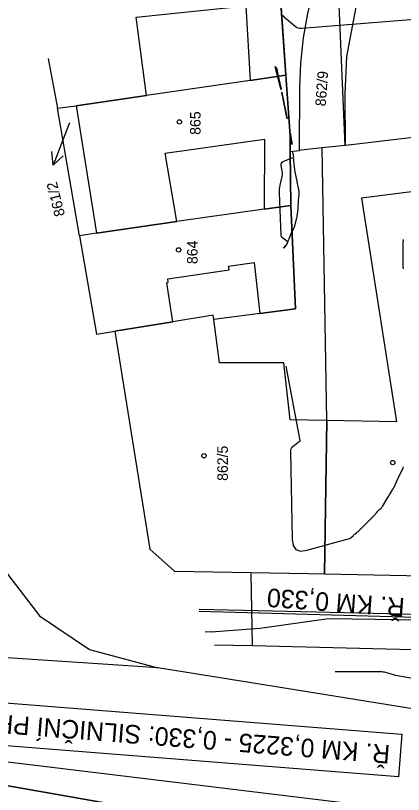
# Model space of a CAD drawing. Extents: x -534481 to -534256, y -1190577 to -1190138.
# Drawn here: x -534381.4 to -534350, y -1190249.6 to -1190186.6 of the extents above; entities that cross this region are included whole.
import ezdxf

# ---------------------------------------------------------------- set-up
doc = ezdxf.new("R2010")
doc.units = 0
for name, color, linetype in [('14', 7, 'Continuous'), ('30', 7, 'Continuous'), ('31', 7, 'Continuous'), ('_N_text', 7, 'Continuous'), ('_rámeček', 7, 'Continuous'), ('_tenka', 7, 'Continuous'), ('Hranice parcel', 7, 'Continuous'), ('Level 30', 7, 'Continuous'), ('Parcelní čísla', 7, 'Continuous'), ('Polygon budovy', 7, 'Continuous'), ('Pop  PČ popisy', 7, 'Continuous'), ('Vrstva 1', 7, 'Continuous'), ('Značky budov', 7, 'Continuous')]:
    doc.layers.add(name, color=color, linetype=linetype)

msp = doc.modelspace()

# ---------------------------------------------------------------- linework, layer by layer
at = {"layer": '14'}
for points in [[(-534362.202, -1190237.552), (-534362.331, -1190231.681)], [(-534316.429, -1190238.25), (-534318.08, -1190238.03), (-534322.04, -1190237.08), (-534332.22, -1190235.41), (-534338.777, -1190234.334), (-534339.342, -1190238.274), (-534345.981, -1190237.953), (-534362.202, -1190237.552), (-534365.29, -1190237.5)]]:
    msp.add_lwpolyline(points, dxfattribs=at)
at = {"layer": '30'}
for points in [[(-534360.382, -1190190.677), (-534360.38, -1190190.668), (-534360.373, -1190190.673), (-534360.359, -1190190.692), (-534360.294, -1190190.794), (-534360.279, -1190190.82), (-534360.266, -1190190.847), (-534360.256, -1190190.875), (-534360.248, -1190190.904), (-534360.158, -1190191.324), (-534359.931, -1190192.369), (-534359.903, -1190192.507), (-534359.895, -1190192.553), (-534359.91, -1190192.508), (-534359.946, -1190192.372), (-534360.377, -1190190.7)], [(-534359.433, -1190194.812), (-534359.44, -1190194.779), (-534359.467, -1190194.648), (-534359.474, -1190194.615), (-534359.481, -1190194.582), (-534359.487, -1190194.55), (-534359.494, -1190194.517), (-534359.728, -1190193.318), (-534359.736, -1190193.278), (-534359.744, -1190193.239), (-534359.753, -1190193.199), (-534359.762, -1190193.159), (-534359.816, -1190192.941), (-534359.818, -1190192.931), (-534359.82, -1190192.922), (-534359.821, -1190192.912), (-534359.822, -1190192.902), (-534359.827, -1190192.864), (-534359.828, -1190192.854), (-534359.829, -1190192.845), (-534359.831, -1190192.835), (-534359.833, -1190192.826), (-534359.846, -1190192.763), (-534359.849, -1190192.752), (-534359.85, -1190192.749), (-534359.849, -1190192.752), (-534359.848, -1190192.763), (-534359.828, -1190192.875), (-534359.824, -1190192.898), (-534359.82, -1190192.922), (-534359.815, -1190192.945), (-534359.809, -1190192.968), (-534359.762, -1190193.159), (-534359.753, -1190193.199), (-534359.744, -1190193.239), (-534359.736, -1190193.278), (-534359.728, -1190193.318), (-534359.494, -1190194.517), (-534359.487, -1190194.55), (-534359.481, -1190194.582), (-534359.474, -1190194.615), (-534359.467, -1190194.648), (-534359.44, -1190194.779), (-534359.433, -1190194.812), (-534359.427, -1190194.845)], [(-534359.42, -1190194.877), (-534359.414, -1190194.91), (-534359.42, -1190194.877), (-534359.427, -1190194.845)], [(-534359.042, -1190196.767), (-534359.053, -1190196.689), (-534359.099, -1190196.379), (-534359.112, -1190196.302), (-534359.126, -1190196.225), (-534359.141, -1190196.148), (-534359.159, -1190196.071), (-534359.141, -1190196.148), (-534359.126, -1190196.225), (-534359.112, -1190196.302), (-534359.099, -1190196.379), (-534359.053, -1190196.689), (-534359.042, -1190196.767), (-534359.032, -1190196.845)], [(-534359.024, -1190196.923), (-534359.017, -1190197.001), (-534359.024, -1190196.923), (-534359.032, -1190196.845)], [(-534359.521, -1190205.171), (-534359.497, -1190205.143), (-534359.476, -1190205.114), (-534359.458, -1190205.083), (-534359.443, -1190205.05), (-534359.391, -1190204.913), (-534359.383, -1190204.88), (-534359.386, -1190204.851), (-534359.399, -1190204.825), (-534359.424, -1190204.802), (-534359.767, -1190204.553), (-534359.826, -1190204.501), (-534359.869, -1190204.439), (-534359.896, -1190204.369), (-534359.907, -1190204.291), (-534360.027, -1190200.91), (-534360.028, -1190200.753), (-534360.019, -1190200.597), (-534359.999, -1190200.442), (-534359.97, -1190200.288), (-534359.813, -1190199.587), (-534359.793, -1190199.476), (-534359.786, -1190199.364), (-534359.791, -1190199.253), (-534359.807, -1190199.141), (-534359.895, -1190198.693), (-534359.901, -1190198.59), (-534359.876, -1190198.502), (-534359.819, -1190198.431), (-534359.731, -1190198.376), (-534359.093, -1190198.089), (-534359.008, -1190198.064), (-534358.946, -1190198.077), (-534358.905, -1190198.126), (-534358.887, -1190198.213), (-534358.859, -1190198.634), (-534358.85, -1190198.739), (-534358.838, -1190198.844), (-534358.823, -1190198.948), (-534358.805, -1190199.052), (-534358.675, -1190199.717), (-534358.67, -1190199.742), (-534358.665, -1190199.767), (-534358.66, -1190199.791), (-534358.655, -1190199.816), (-534358.635, -1190199.914), (-534358.63, -1190199.938), (-534358.625, -1190199.963), (-534358.62, -1190199.987), (-534358.615, -1190200.012), (-534358.488, -1190200.651), (-534358.472, -1190200.748), (-534358.464, -1190200.845), (-534358.463, -1190200.943), (-534358.469, -1190201.041), (-534358.518, -1190201.525), (-534358.523, -1190201.578), (-534358.526, -1190201.63), (-534358.529, -1190201.683), (-534358.531, -1190201.735), (-534358.535, -1190201.946), (-534358.537, -1190201.998), (-534358.54, -1190202.051), (-534358.544, -1190202.103), (-534358.549, -1190202.155), (-534358.609, -1190202.646), (-534358.622, -1190202.745), (-534358.638, -1190202.843), (-534358.658, -1190202.941), (-534358.68, -1190203.039), (-534358.819, -1190203.605), (-534358.837, -1190203.67), (-534358.859, -1190203.733), (-534358.886, -1190203.795), (-534358.916, -1190203.855), (-534359.046, -1190204.093), (-534359.077, -1190204.153), (-534359.107, -1190204.214), (-534359.135, -1190204.275), (-534359.161, -1190204.338), (-534359.337, -1190204.776), (-534359.351, -1190204.811), (-534359.364, -1190204.845), (-534359.377, -1190204.879), (-534359.391, -1190204.913), (-534359.443, -1190205.05), (-534359.458, -1190205.083), (-534359.476, -1190205.114), (-534359.497, -1190205.143), (-534359.521, -1190205.171), (-534359.709, -1190205.362)]]:
    msp.add_lwpolyline(points, close=True, dxfattribs=at)
for points in [[(-534358.967, -1190197.621), (-534358.901, -1190198.002)], [(-534350.003, -1190207.033), (-534350.019, -1190206.907), (-534350.022, -1190206.876), (-534350.025, -1190206.844), (-534350.026, -1190206.813), (-534350.027, -1190206.781), (-534350.027, -1190204.906), (-534350.026, -1190204.875), (-534350.024, -1190204.845), (-534350.021, -1190204.814), (-534350.016, -1190204.784), (-534349.996, -1190204.662)], [(-534359.53, -1190214.922), (-534358.38, -1190220.935), (-534358.379, -1190220.942), (-534358.379, -1190220.949), (-534358.38, -1190220.957), (-534358.382, -1190220.964), (-534358.39, -1190220.992), (-534358.392, -1190220.999), (-534358.396, -1190221.005), (-534358.4, -1190221.011), (-534358.405, -1190221.015), (-534358.964, -1190221.454), (-534359.047, -1190221.534), (-534359.106, -1190221.626), (-534359.14, -1190221.729), (-534359.15, -1190221.845), (-534359.013, -1190228.914), (-534358.929, -1190229.427), (-534358.702, -1190229.748), (-534358.33, -1190229.875), (-534357.814, -1190229.811), (-534354.382, -1190228.87), (-534354.337, -1190228.855), (-534354.295, -1190228.834), (-534354.257, -1190228.807), (-534354.222, -1190228.776), (-534354.081, -1190228.632), (-534354.049, -1190228.601), (-534354.017, -1190228.571), (-534353.984, -1190228.541), (-534353.95, -1190228.513), (-534353.812, -1190228.403), (-534353.778, -1190228.375), (-534353.745, -1190228.346), (-534353.712, -1190228.316), (-534353.681, -1190228.285), (-534352.302, -1190226.907), (-534352.272, -1190226.875), (-534352.241, -1190226.843), (-534352.212, -1190226.811), (-534352.183, -1190226.777), (-534352.069, -1190226.643), (-534352.04, -1190226.61), (-534352.01, -1190226.578), (-534351.978, -1190226.548), (-534351.945, -1190226.518), (-534351.81, -1190226.404), (-534351.778, -1190226.375), (-534351.749, -1190226.343), (-534351.722, -1190226.308), (-534351.698, -1190226.272), (-534351.266, -1190225.547), (-534351.224, -1190225.476), (-534351.181, -1190225.406), (-534351.139, -1190225.336), (-534351.096, -1190225.265), (-534350.925, -1190224.985), (-534350.883, -1190224.914), (-534350.843, -1190224.843), (-534350.805, -1190224.77), (-534350.769, -1190224.696), (-534350.573, -1190224.289), (-534350.529, -1190224.196), (-534350.485, -1190224.103), (-534350.441, -1190224.01), (-534350.397, -1190223.917), (-534350.064, -1190223.204), (-534350.048, -1190223.168), (-534350.031, -1190223.132), (-534350.014, -1190223.096), (-534349.997, -1190223.06)]]:
    msp.add_lwpolyline(points, dxfattribs=at)
at = {"layer": '31'}
for points in [[(-534349.078, -1190186.866), (-534358.236, -1190187.618), (-534358.385, -1190187.617), (-534358.524, -1190187.587), (-534358.654, -1190187.53), (-534358.775, -1190187.444), (-534359.437, -1190186.876), (-534359.455, -1190186.86), (-534359.473, -1190186.844), (-534359.49, -1190186.828), (-534359.508, -1190186.812), (-534359.577, -1190186.746), (-534359.594, -1190186.729), (-534359.611, -1190186.712), (-534359.628, -1190186.696), (-534359.644, -1190186.678), (-534359.71, -1190186.609), (-534359.726, -1190186.592), (-534359.741, -1190186.573), (-534359.756, -1190186.555)], [(-534355.528, -1190239.606), (-534355.041, -1190239.606), (-534354.862, -1190239.606), (-534354.505, -1190239.606), (-534354.386, -1190239.606), (-534353.934, -1190239.606), (-534353.743, -1190239.606), (-534353.553, -1190239.606), (-534353.041, -1190239.606), (-534352.862, -1190239.606), (-534352.505, -1190239.606), (-534352.386, -1190239.606), (-534351.934, -1190239.606), (-534351.839, -1190239.609), (-534351.745, -1190239.619), (-534351.652, -1190239.636), (-534351.56, -1190239.658), (-534350.805, -1190239.874), (-534350.754, -1190239.888), (-534350.703, -1190239.903), (-534350.69, -1190239.906), (-534350.677, -1190239.91), (-534350.664, -1190239.912), (-534350.651, -1190239.915), (-534349.281, -1190240.167)]]:
    msp.add_lwpolyline(points, dxfattribs=at)
at = {"layer": '_N_text'}
msp.add_lwpolyline([(-534396.161, -1190241.055), (-534350.137, -1190244.697), (-534350.409, -1190248.138), (-534396.433, -1190244.496)], close=True, dxfattribs=at)
at = {"layer": '_rámeček'}
for points in [[(-534261.668, -1190163.461), (-534407.912, -1190137.674), (-534426.145, -1190241.079), (-534333.072, -1190257.49)], [(-534333.072, -1190257.49), (-534426.145, -1190241.079), (-534444.378, -1190344.484), (-534298.134, -1190370.27)]]:
    msp.add_lwpolyline(points, dxfattribs=at)
at = {"layer": '_tenka'}
msp.add_lwpolyline([(-534366.521, -1190234.728), (-534348.981, -1190235.231), (-534336.32, -1190236.042), (-534316.711, -1190239.297)], dxfattribs=at)
at = {"layer": 'Hranice parcel'}
for p, q in [((-534354.73, -1190197.08), (-534355.5, -1190178.16)), ((-534360.26, -1190180.57), (-534359.52, -1190191.38)), ((-534378.724, -1190190.024), (-534377.99, -1190194.05)), ((-534377.99, -1190194.05), (-534376.48, -1190193.87)), ((-534376.21, -1190204.38), (-534377.99, -1190194.05)), ((-534376.48, -1190193.87), (-534374.83, -1190204.15)), ((-534354.73, -1190197.08), (-534356.58, -1190197.27)), ((-534359.16, -1190197.55), (-534358.42, -1190197.47)), ((-534359.16, -1190197.55), (-534359.11, -1190201.91)), ((-534374.83, -1190204.15), (-534376.21, -1190204.38)), ((-534369.86, -1190239.33), (-534400.65, -1190237.26))]:
    msp.add_line(p, q, dxfattribs=at)
for points in [[(-534349.263, -1190148.015), (-534349.33, -1190148.26), (-534348.67, -1190162.35), (-534348.64, -1190164.35), (-534348.75, -1190166.39), (-534349.02, -1190168.37), (-534349.42, -1190170.33), (-534353.85, -1190185.89), (-534354.6, -1190189.86), (-534354.75, -1190192.89), (-534354.73, -1190197.08)], [(-534358.42, -1190197.47), (-534358.38, -1190192.4), (-534358.3, -1190190.41), (-534358.1, -1190188.37), (-534357.75, -1190186.39), (-534357.29, -1190184.43), (-534355.5, -1190178.16)], [(-534393.173, -1190187.476), (-534393.12, -1190187.67), (-534387.8, -1190211.29), (-534384.29, -1190226.41), (-534381.99, -1190231.76), (-534379.42, -1190235.11), (-534375.39, -1190237.83), (-534369.86, -1190239.33)], [(-534359.52, -1190191.38), (-534362.41, -1190191.8), (-534370.79, -1190193.02), (-534376.48, -1190193.87)], [(-534359.52, -1190191.38), (-534359.17, -1190196.28), (-534359.16, -1190197.55)], [(-534347.19, -1190196.18), (-534354, -1190197), (-534354.73, -1190197.08)], [(-534356.58, -1190197.27), (-534358.27, -1190197.45), (-534358.42, -1190197.47)], [(-534356.39, -1190231.73), (-534356.2, -1190219.31), (-534356.58, -1190197.27)], [(-534359.11, -1190201.91), (-534361.27, -1190202.22), (-534368.34, -1190203.23), (-534374.83, -1190204.15)], [(-534359.11, -1190201.91), (-534358.74, -1190210.28), (-534361.62, -1190210.66), (-534365.33, -1190211.15), (-534365.38, -1190210.8), (-534368.64, -1190211.34), (-534373.35, -1190212.08)], [(-534376.21, -1190204.38), (-534374.83, -1190212.32), (-534373.35, -1190212.08)], [(-534373.35, -1190212.08), (-534370.52, -1190229.73), (-534368.51, -1190231.49), (-534357.69, -1190231.7), (-534356.39, -1190231.73)], [(-534356.39, -1190231.73), (-534347.08, -1190231.91), (-534344.61, -1190231.96)], [(-534360.304, -1190240.857), (-534369.86, -1190239.33)], [(-534346.43, -1190243.1), (-534360.304, -1190240.857)], [(-534372.221, -1190248.144), (-534389.59, -1190246.03), (-534397.44, -1190245.57), (-534405.02, -1190245.73), (-534413.23, -1190246.52)], [(-534346.75, -1190251.25), (-534347.61, -1190251.14), (-534372.221, -1190248.144)]]:
    msp.add_lwpolyline(points, dxfattribs=at)
at = {"layer": 'Level 30'}
for p, q in [((-534361.62, -1190236.12), (-534356.06, -1190235.32)), ((-534356.06, -1190235.32), (-534346.56, -1190235.48)), ((-534365.55, -1190236.4), (-534361.62, -1190236.12)), ((-534365.55, -1190236.4), (-534366.03, -1190236.43))]:
    msp.add_line(p, q, dxfattribs=at)
at = {"layer": 'Polygon budovy'}
msp.add_lwpolyline([(-534378.724, -1190190.024), (-534377.99, -1190194.05), (-534376.48, -1190193.87), (-534370.79, -1190193.02), (-534371.63, -1190186.69), (-534362.74, -1190185.76), (-534362.41, -1190191.8), (-534359.52, -1190191.38), (-534360.26, -1190180.57), (-534364.79, -1190180.95), (-534372.94, -1190181.67), (-534373.938, -1190181.797)], dxfattribs=at)
for points in [[(-534359.17, -1190196.28), (-534359.52, -1190191.38), (-534362.41, -1190191.8), (-534370.79, -1190193.02), (-534376.48, -1190193.87), (-534374.83, -1190204.15), (-534368.34, -1190203.23), (-534369.28, -1190197.69), (-534361.25, -1190196.57), (-534361.27, -1190202.22), (-534359.11, -1190201.91), (-534359.16, -1190197.55)], [(-534356.39, -1190231.73), (-534347.08, -1190231.91), (-534344.61, -1190231.96), (-534344.81, -1190226.96), (-534345.1, -1190219.6), (-534346.8, -1190200.49), (-534353.41, -1190201.32), (-534350.57, -1190219.42), (-534356.2, -1190219.31)], [(-534374.83, -1190204.15), (-534376.21, -1190204.38), (-534374.83, -1190212.32), (-534373.35, -1190212.08), (-534368.64, -1190211.34), (-534369.15, -1190208.17), (-534369.02, -1190208.12), (-534369.05, -1190207.85), (-534364.11, -1190207.12), (-534364.16, -1190206.82), (-534362.08, -1190206.54), (-534361.62, -1190210.66), (-534358.74, -1190210.28), (-534359.11, -1190201.91), (-534361.27, -1190202.22), (-534368.34, -1190203.23)], [(-534370.52, -1190229.73), (-534368.51, -1190231.49), (-534357.69, -1190231.7), (-534356.39, -1190231.73), (-534356.2, -1190219.31), (-534359.16, -1190219.26), (-534359.68, -1190214.65), (-534364.87, -1190214.64), (-534365.33, -1190211.15), (-534365.38, -1190210.8), (-534368.64, -1190211.34), (-534373.35, -1190212.08)]]:
    msp.add_lwpolyline(points, close=True, dxfattribs=at)
at = {"layer": 'Pop  PČ popisy'}
for p, q in [((-534377.02, -1190195.23), (-534377.26, -1190195.86)), ((-534377.26, -1190195.86), (-534378.335, -1190198.662)), ((-534378.335, -1190198.662), (-534378.444, -1190197.547)), ((-534378.335, -1190198.662), (-534377.509, -1190197.906))]:
    msp.add_line(p, q, dxfattribs=at)
at = {"layer": 'Vrstva 1'}
msp.add_lwpolyline([(-534366.535, -1190234.586), (-534360.579, -1190234.722), (-534348.99, -1190234.986)], dxfattribs=at)
at = {"layer": 'Značky budov'}
for centre in [(-534368.124, -1190195.168), (-534368.188, -1190205.51), (-534366.136, -1190222.163), (-534350.877, -1190222.724)]:
    msp.add_circle(centre, 0.175, dxfattribs=at)

# ---------------------------------------------------------------- texts
at = {"layer": '_N_text'}
for s, rotation, p in [('Ř. KM 0,330', 175.83222, (-534349.858, -1190233.698)), ('Ř. KM 0,3225 - 0,330: SILNIČNÍ PROPUSTEK', 175.5, (-534351.039, -1190245.582))]:
    msp.add_text(s, height=1.5, rotation=rotation, dxfattribs=at).set_placement(p)
at = {"layer": 'Parcelní čísla'}
for s, rotation, p in [('862/9', 86, (-534356.294, -1190193.919)), ('865', 90, (-534366.411, -1190196.205)), ('861/2', 104, (-534377.363, -1190202.695)), ('864', 90, (-534366.653, -1190206.662)), ('862/5', 90, (-534364.205, -1190224.196))]:
    msp.add_text(s, height=0.85, rotation=rotation, dxfattribs=at).set_placement(p)

doc.saveas('drawing.dxf')
